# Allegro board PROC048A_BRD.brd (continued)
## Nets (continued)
3V3_A: C11.1 C40.1 C41.1 FL4.1 L3.2 R14.1
5V: C25.2 C26.2 C27.1 C28.1 C99.1 C100.1 D1.2(ANODE) D2.2(ANODE) D3.2(ANODE) D4.2(ANODE) FL8.2 LD10.2(ANODE) R1.2 R2.2 U1.11(PVIN1) U1.12(PVIN2) U1.13(PVIN3) U1.14(PVIN4) U2.11(PVIN1) U2.12(PVIN2) U2.13(PVIN3) U2.14(PVIN4)
GND: C1.2 C2.2 C3.2 C4.2 C7.2 C8.2 C9.2 C12.2 C13.2 C14.2 C15.2 C16.2 C17.2 C22.2 C23.2 C24.2 C25.1 C26.1 C27.2 C28.2 C29.2 C30.2 C31.2 C32.2 C33.2 C34.2 C35.2 C36.2 C37.2 C38.2 C39.2 C40.2 C41.2 C42.2 C43.2 C44.2 C45.2 C46.2 C47.2 C48.2 C49.1 C50.1 C51.2 C52.2 C53.2 C54.2 C55.2 C56.2 C57.2 C59.2 C60.2 C61.2 C62.2 C63.2 C64.2 C65.2 C66.2 C67.2 C68.2 C69.2 C70.2 C71.2 C72.2 C73.2 C74.1 C75.1 C76.2 C77.2 C78.2 C79.1 C80.1 C81.1 C82.2 C83.2 C84.1 C85.2 C86.2 C87.2 C88.2 C89.1 C90.2 C91.2 C92.2 C93.2 C94.2 C95.1 C96.1 C97.2 C98.2 C99.2 C100.2 C101.2 C102.2 C103.2 C104.2 C105.2 C106.2 C107.2 C108.2 C109.2 C110.2 C111.2 C112.2 C113.2 C114.2 C115.2 C116.1 C117.2 C118.1 C119.1 C120.1 C121.2 C122.1 C123.2 C124.2 C125.1 C126.2 C127.1 C128.1 C129.2 C130.2 C131.2 C132.1 C133.1 C134.1 C135.2 C136.2 C137.1 C138.1 C139.2 C140.1 C141.2 C142.1 C143.1 C144.2 C145.1 C146.1 C147.2 C148.1 C149.1 C150.1 C151.1 C152.2 C153.1 C154.2 C155.2 C156.2 C157.2 C158.1 C159.2 C160.2 C161.1 C162.1 C163.2 C164.1 C165.2 C166.1 C167.2 C168.1 C169.1 C170.1 C171.1 C172.2 C173.1 C174.2 C175.2 C176.1 C177.2 C178.2 C179.2 C180.2 C181.2 C182.2 C183.2 C184.1 C185.1 C186.2 C187.2 C188.1 C189.2 C190.2 C191.1 C192.1 C193.2 C194.1 C195.2 C196.2 C197.2 C198.2 C199.2 C200.1 C201.2 C202.1 C203.2 C204.2 C205.2 C206.1 C207.2 C208.2 C209.1 C210.1 C211.1 C212.1 C213.2 C214.1 C215.2 C216.2 D5.2(ANODE) D6.2(ANODE) D7.2(ANODE) D8.2(ANODE) D9.3(GND) D10.2 D11.3(GND) D12.2 D13.2 D14.2 D15.2(A) D16.2(ANODE) FL7.1 J1.5 J2.2 J2.3 J3.18 J3.24 J3.30 J3.36 J3.42 J3.48 J3.54 J3.60 J3.61 J3.62 J3.63 J3.64 J4.4 J4.5 J5.6(VSS) J5.12(CD2) Q1.2(EMITTER) R13.2 R15.2 R18.2 R19.2 R21.2 R25.1 R27.1 R39.2 R42.1 R44.2 R46.2 R49.2 R56.1 R59.1 R66.1 R109.1 R135.2 R155.2 R185.1 R187.1 R188.1 R190.2 R196.2 R205.2 R206.2 R207.2 S1.2 S1.3 S1.4 SW1.4 SW1.5 SW1.6 SW2.9 SW2.10 SW2.11 SW2.12 SW2.13 SW2.14 SW2.15 SW2.16 SW4.3 SW4.4 SW5.3 SW5.4 SW6.3 SW6.4 SW7.3 SW7.4 TP5.1(TP) TP32.1(TP) TP33.1(TP) U1.5(GND) U1.17(DAP) U2.5(GND) U2.17(DAP) U3.1(GND1) U3.5(GND2) U3.10(AGND) U3.11(GND3) U3.13(TEST) U3.15(GND4) U3.25(GND5) U3.35(GND6) U3.47(GND7) U3.51(GND8) U4.5(VSS) U5.4(GND) U5.9(EPAD) U6.65(EP) U7.4(GND) U8.3(GND) U9.3(GND) U10.A1(VSS#A1) U10.A8(VSS#A8) U10.B1(VSS#B1) U10.B2(VSSQ#B2) U10.B8(VSSQ#B8) U10.C9(VSSQ#C9) U10.D1(VSSQ#D1) U10.D8(VSS#D8) U10.D9(VSSQ#D9) U10.F2(VSS#F2) U10.F8(VSS#F8) U10.J1(VSS#J1) U10.J9(VSS#J9) U10.L1(VSS#L1) U10.L9(VSS#L9) U10.N1(VSS#N1) U10.N9(VSS#N9) U11.A1(VSS#A1) U11.A8(VSS#A8) U11.B1(VSS#B1) U11.B2(VSSQ#B2) U11.B8(VSSQ#B8) U11.C9(VSSQ#C9) U11.D1(VSSQ#D1) U11.D8(VSS#D8) U11.D9(VSSQ#D9) U11.F2(VSS#F2) U11.F8(VSS#F8) U11.J1(VSS#J1) U11.J9(VSS#J9) U11.L1(VSS#L1) U11.L9(VSS#L9) U11.N1(VSS#N1) U11.N9(VSS#N9) U12.B7(GND#B7) U12.B14(GND#B14) U12.C19(GND#C19) U12.D4(GND#D4) U12.F7(GND#F7) U12.F8(GND#F8) U12.F13(GND#F13) U12.F14(GND#F14) U12.G4(GND#G4) U12.G6(GND#G6) U12.G7(GND#G7) U12.G8(GND#G8) U12.G9(GND#G9) U12.G10(GND#G10) U12.G11(GND#G11) U12.G12(GND#G12) U12.G13(GND#G13) U12.G14(GND#G14) U12.G15(GND#G15) U12.G17(GND#G17) U12.H19(GND#H19) U12.J2(GND#J2) U12.J7(GND#J7) U12.J9(GND#J9) U12.J10(GND#J10) U12.J11(GND#J11) U12.J12(GND#J12) U12.J14(GND#J14) U12.K6(GND#K6) U12.K7(GND#K7) U12.K9(GND#K9) U12.K10(GND#K10) U12.K11(GND#K11) U12.K12(GND#K12) U12.K14(GND#K14) U12.K15(GND#K15) U12.L9(GND#L9) U12.L10(GND#L10) U12.L11(GND#L11) U12.L12(GND#L12) U12.M2(GND#M2) U12.M7(GND#M7) U12.M9(GND#M9) U12.M10(GND#M10) U12.M11(GND#M11) U12.M12(GND#M12) U12.M14(GND#M14) U12.M16(GND#M16) U12.N6(GND#N6) U12.N7(GND#N7) U12.N14(GND#N14) U12.N15(GND#N15) U12.P7(GND#P7) U12.P8(GND#P8) U12.P11(GND#P11) U12.P12(GND#P12) U12.P13(GND#P13) U12.P14(GND#P14) U12.R19(GND#R19) U12.U7(GNDA#U7) U12.U8(GNDA#U8) U12.U9(GNDA#U9) U12.U10(GNDA#U10) U12.U11(GNDA#U11) U12.U12(GNDA#U12) U12.U13(GNDA#U13) U12.U14(GNDA#U14) U12.V5(GNDA#V5) U12.V6(GNDA#V6) U12.V7(GNDA#V7) U12.V8(GNDA#V8) U12.V9(GNDA#V9) U12.V12(GNDA#V12) U12.V13(GNDA#V13) U12.V14(GNDA#V14) U12.V15(GNDA#V15) U12.V16(GNDA#V16) U12.V19(GNDA#V19) U12.V20(GNDA#V20) U12.W6(GNDA#W6) U12.W7(GNDA#W7) U12.W12(GNDA#W12) U12.W15(GNDA#W15) U12.W16(GNDA#W16) U12.W19(GNDA#W19) U12.W20(REFCLKN_D1) U12.Y5(HDRXP0_D0CH0) U12.Y6(HDRXN0_D0CH0) U12.Y7(HDRXP0_D0CH1) U12.Y8(HDRXN0_D0CH1) U12.Y11(REFCLKP_D0) U12.Y12(REFCLKN_D0) U12.Y14(HDRXP0_D1CH0) U12.Y15(HDRXN0_D1CH0) U12.Y16(HDRXP0_D1CH1) U12.Y17(HDRXN0_D1CH1) U12.Y19(REFCLKP_D1) U13.3(GND) U14.10(VSS) U15.1(GND#1) U15.5(GND#5) U15.10(AGND) U15.11(GND#11) U15.13(TEST) U15.15(GND#15) U15.25(GND#25) U15.35(GND#35) U15.47(GND#47) U15.51(GND#51) U16.5(GND) U17.3(GND#3) U17.8(GND#8) U18.3(GND#3) U18.8(GND#8) U19.4(PGND) U19.8(GND) U19.11(PAD) U20.5(VSS) Y1.2 Y1.4 Y3.2 Y3.4
GND_EARTH: C49.2 C50.2 R41.1
GND_SDCD: FL7.2 J5.10 J5.11 J5.13 J5.14
VCC5V_CONN: C76.1 C77.1 C78.1 C79.2 J3.1 J3.2 J3.3 SW3.3
VCC5V_EXT: J2.1 SW3.1
VCC_1V1: C10.1 C36.1 C37.1 FL2.1 L1.2 R12.1
VCC_AUX: C124.1 C137.2 C144.1 C199.1 C203.1 FL9.1 U12.F6(VCCAUX#F6) U12.F15(VCCAUX#F15) U12.P6(VCCAUX#P6) U12.P15(VCCAUX#P15) U12.V10(VCCAUXA0#V10) U12.V11(VCCAUXA0#V11) U12.V17(VCCAUXA1#V17) U12.V18(VCCAUXA1#V18)
VCC_CORE: C151.2 C160.1 C171.2 C172.1 C173.2 C174.1 C182.1 C183.1 C188.2 C194.2 FL2.2 U12.H8(VCC#H8) U12.H9(VCC#H9) U12.H10(VCC#H10) U12.H11(VCC#H11) U12.H12(VCC#H12) U12.H13(VCC#H13) U12.J8(VCC#J8) U12.J13(VCC#J13) U12.K8(VCC#K8) U12.K13(VCC#K13) U12.L8(VCC#L8) U12.L13(VCC#L13) U12.M8(VCC#M8) U12.M13(VCC#M13) U12.N8(VCC#N8) U12.N9(VCC#N9) U12.N10(VCC#N10) U12.N11(VCC#N11) U12.N12(VCC#N12) U12.N13(VCC#N13)
VCCHTX: C63.1 C64.1 C209.2 C211.2 C212.2 FL5.2 R214.1 U12.T6(VCCA0#T6) U12.T15(VCCA1#T15) U12.U6(VCCA0#U6) U12.U15(VCCA1#U15)
VCCHTX_1V1: C57.1 C58.1 FL5.1 FL6.1 R45.1 U5.1(OUT1) U5.2(OUT2)
VCCHTX_C: C200.2 C206.2 C210.2 R214.2 U12.T7(VCCHTX0_D0CH0) U12.T8(VCCHRX0_D0CH0) U12.T9(VCCHRX1_D0CH1) U12.T10(VCCHTX1_D0CH1) U12.T11(VCCHTX0_D1CH0) U12.T12(VCCHRX0_D1CH0) U12.T13(VCCHRX1_D1CH1) U12.T14(VCCHTX1_D1CH1)
12MHZ_OSCI: C31.1 U3.2(OSCI) Y1.1
12MHZ_OSCI1: C93.1 U15.2(OSCI) Y3.1
12MHZ_OSCO: C29.1 U3.3(OSCO) Y1.3
12MHZ_OSCO1: C91.1 U15.3(OSCO) Y3.3
AR1243_LVDS_MODE: R175.2 SW2.3 U12.C6(PT11A)
BST1_REGA: C19.2 D7.1(CATHODE) L2.1 U1.15(SW1)
BST1_REGB: C21.2 D8.1(CATHODE) L4.1 U2.15(SW1)
BST2_REGA: C18.2 D5.1(CATHODE) L1.1 U1.10(SW2)
BST2_REGB: C20.2 D6.1(CATHODE) L3.1 U2.10(SW2)
C_RGMII_RXC: R47.2 U6.43(RX_CLK)
C_RGMII_RXCTL: R63.2 R64.2 R66.2 U6.53(RX_DV/RX_CTRL)
C_RGMII_RXD0: R48.1 R184.2 R185.2 U6.44(RX_D0)
C_RGMII_RXD1: R60.1 U6.45(RX_D1)
C_RGMII_RXD2: R61.1 R186.1 R187.2 U6.46(RX_D2)
C_RGMII_RXD3: R62.1 U6.47(RX_D3)
C_RGMII_RXD4: R188.2 R189.1 U6.48(RX_D4/GPIO)
C_RGMII_RXD6: R59.2 R65.1 U6.50(RX_D6/GPIO)
C_RGMII_RXD7: R55.1 R56.2 U6.51(RX_D7/GPIO)
CAPTURE_START: C89.2 R151.1 R153.2 U12.U1(PB6A/D5/MISO2/IO5)
CFG0: R217.2 S1.7 U12.U4(CFG_0)
CFG1: R216.2 S1.6 U12.T4(CFG_1)
CFG2: R215.2 S1.5 U12.R4(CFG_2)
CONFIG_VIA_HW: R177.2 SW2.5 U12.A7(PT18A)
CONN_SPI_CLK: J3.9 R91.2 R92.2
CONN_SPI_CSN: J3.7 R85.2 R86.2
CONN_SPI_MISO: J3.12 R90.2 R96.2
CONN_SPI_MOSI: J3.11 R99.2 R101.2
DATA_TRANS_PROG_LED1: LD1.1(CATHODE) U12.E6(PT6A)
DDR3_A0: RA6.6 U10.K3(A0) U11.K3(A0) U12.K18(PR41D)
DDR3_A1: RA7.7 U10.L7(A1) U11.L7(A1) U12.G20(PR38D)
DDR3_A2: RA6.5 U10.L3(A2) U11.L3(A2) U12.G19(PR41A/GR_PCLK2_1)
DDR3_A3: RA9.8 U10.K2(A3) U11.K2(A3) U12.J18(PR41C/GR_PCLK2_0)
DDR3_A4: RA7.8 U10.L8(A4) U11.L8(A4) U12.J19(PR44A/PCLKT2_1/S2_OUT)
DDR3_A5: RA5.5 U10.L2(A5) U11.L2(A5) U12.J16(PR20D)
DDR3_A6: RA8.8 U10.M8(A6) U11.M8(A6) U12.E20(PR38A)
DDR3_A7: RA5.6 U10.M2(A7) U11.M2(A7) U12.K17(PR29B)
DDR3_A8: RA8.7 U10.N8(A8) U11.N8(A8) U12.J20(PR44C/PCLKT2_0/S3_IN)
DDR3_A9: RA5.7 U10.M3(A9) U11.M3(A9) U12.D20(PR35C/VREF1_2)
DDR3_A10: RA6.8 U10.H7(A10/AP) U11.H7(A10/AP) U12.K19(PR44B/PCLKC2_1)
DDR3_A11: RA8.6 U10.M7(A11) U11.M7(A11) U12.F19(PR38B)
DDR3_A12: RA7.5 U10.K7(A12/BC#) U11.K7(A12/BC#) U12.F20(PR38C)
DDR3_A13: RA5.8 U10.N3(A13) U11.N3(A13) U12.L19(PR47C/PCLKT3_0/S4_IN)
DDR3_A14: RA8.5 U10.N7(A14) U11.N7(A14) U12.K16(PR29A)
DDR3_A15: RA6.7 U10.J7(A15) U11.J7(A15) U12.J17(PR20C)
DDR3_BA0: RA9.7 U10.J2(BA0) U11.J2(BA0) U12.D19(PR35B/S2_IN)
DDR3_BA1: RA7.6 U10.K8(BA1) U11.K8(BA1) U12.C20(PR35A/S1_OUT)
DDR3_BA2: RA9.6 U10.J3(BA2) U11.J3(BA2) U12.H17(PR20B)
DDR3_CASN: RA10.7 U10.G3(CAS#) U11.G3(CAS#) U12.E19(PR35D)
DDR3_CK: R210.1 U10.F7(CK) U11.F7(CK) U12.U18(PR92A/LRC_GPLL0T_MFGOUT1)
DDR3_CKE: R191.1 U10.G9(CKE) U11.G9(CKE) U12.L20(PR47A/PCLKT3_1/S3_OUT)
DDR3_CKN: R209.1 U10.G7(CK#) U11.G7(CK#) U12.U17(PR92B/LRC_GPLL0C_MFGOUT1)
DDR3_CSN: RA9.5 U10.H2(CS#) U11.H2(CS#) U12.T17(PR92D/LRC_GPLL0C_IN/S7_OUT)
DDR3_DM0: U11.B7(DM/TDQS) U12.U19(PR89C/LRC_GPLL0T_MFGOUT2)
DDR3_DM1: U10.B7(DM/TDQS) U12.R17(PR56D)
DDR3_DQ0: U11.B3(DQ0) U12.N20(PR83B/S6_IN)
DDR3_DQ1: U11.C7(DQ1) U12.P19(PR83C)
DDR3_DQ2: U11.C2(DQ2) U12.N19(PR83A/S5_OUT)
DDR3_DQ3: U11.C8(DQ3) U12.R20(PR86B/S7_IN)
DDR3_DQ4: U11.E3(NF/DQ4) U12.U20(PR86D)
DDR3_DQ5: U11.E8(NF/DQ5) U12.P18(PR83D)
DDR3_DQ6: U11.D2(NF/DQ6) U12.U16(PR92C/LRC_GPLL0T_IN)
DDR3_DQ7: U11.E7(NF/DQ7) U12.P20(PR86A/S6_OUT)
DDR3_DQ8: U10.B3(DQ0) U12.M19(PR47D/PCLKC3_0)
DDR3_DQ9: U10.C7(DQ1) U12.L16(PR50A/GR_PCLK3_0)
DDR3_DQ10: U10.C2(DQ2) U12.R16(PR56C/S5_IN)
DDR3_DQ11: U10.C8(DQ3) U12.N17(PR56A/S4_OUT)
DDR3_DQ12: U10.E3(NF/DQ4) U12.M20(PR47B/PCLKC3_1)
DDR3_DQ13: U10.E8(NF/DQ5) U12.N18(PR53C)
DDR3_DQ14: U10.D2(NF/DQ6) U12.L18(PR50C/GR_PCLK3_1)
DDR3_DQ15: U10.E7(NF/DQ7) U12.M18(PR50D)
DDR3_DQS0: U11.C3(DQS) U12.T19(PR89A)
DDR3_DQS0N: U11.D3(DQS#) U12.R18(PR89B)
DDR3_DQS1: U10.C3(DQS) U12.N16(PR53A)
DDR3_DQS1N: U10.D3(DQS#) U12.M17(PR53B)
DDR3_ODT: RA10.8 U10.G1(ODT) U11.G1(ODT) U12.T16(PR77A)
DDR3_RASN: RA10.5 U10.F3(RAS#) U11.F3(RAS#) U12.H20(PR41B)
DDR3_RSTN: R69.2 TP13.1(TP) U10.N2(RESET#) U11.N2(RESET#) U12.H18(PR20A)
DDR3_VDD: C74.2 C75.2 C128.2 C129.1 C130.1 C134.2 C135.1 C138.2 C146.2 C152.1 C154.1 C155.1 C161.2 C164.2 C165.1 C168.2 C169.2 C170.2 C178.1 C184.2 C185.2 C186.1 C189.1 C190.1 C192.2 C193.1 C195.1 C196.1 C197.1 C198.1 C207.1 C208.1 FL10.2 U10.A2(VDD#A2) U10.A9(VDD#A9) U10.B9(VDDQ#B9) U10.C1(VDDQ#C1) U10.D7(VDD#D7) U10.E2(VDDQ#E2) U10.E9(VDDQ#E9) U10.G2(VDD#G2) U10.G8(VDD#G8) U10.K1(VDD#K1) U10.K9(VDD#K9) U10.M1(VDD#M1) U10.M9(VDD#M9) U11.A2(VDD#A2) U11.A9(VDD#A9) U11.B9(VDDQ#B9) U11.C1(VDDQ#C1) U11.D7(VDD#D7) U11.E2(VDDQ#E2) U11.E9(VDDQ#E9) U11.G2(VDD#G2) U11.G8(VDD#G8) U11.K1(VDD#K1) U11.K9(VDD#K9) U11.M1(VDD#M1) U11.M9(VDD#M9)
DDR3_VREF: C132.2 R199.1 U19.6(REFOUT)
DDR3_VTT: C113.1 C114.1 C115.1 C116.2 C117.1 C118.2 C119.2 C120.2 C121.1 C122.2 C123.1 C133.2 C136.1 C141.1 C145.2 C150.2 C157.1 C179.1 C180.1 C181.1 R191.2 R197.1 RA5.1 RA5.2 RA5.3 RA5.4 RA6.1 RA6.2 RA6.3 RA6.4 RA7.1 RA7.2 RA7.3 RA7.4 RA8.1 RA8.2 RA8.3 RA8.4 RA9.1 RA9.2 RA9.3 RA9.4 RA10.1 RA10.2 RA10.3 RA10.4 U19.3(VO) U19.5(VOSNS)
DDR3_WEN: RA10.6 U10.H3(WE#) U11.H3(WE#) U12.K20(PR44D/PCLKC2_0)
DDR_1V35: C5.1 C38.1 C39.1 FL3.1 L2.2 R10.1
DDR_FULL_LED7: LD6.1(CATHODE) U12.E10(PT56B)
DMM_CLK: J3.15 R94.2
DMM_CLK_C: R94.1 U12.G1(PL47D/PCLKC6_0)
DMM_MUX_CTL: J3.16 R120.2
DMM_MUX_CTL_C: R120.1 U12.P5(PL83D/D14/IO14)
DMM_SYNC: J3.17 R95.2
DMM_SYNC_C: R95.1 U12.H2(PL47C/PCLKT6_0)
DONE: R104.2 R107.2 TP2.1(TP) U12.Y3(DONE)
DP0: J3.19 RA1.5
DP0_C: RA1.4 U12.H1(PL53C)
DP1: J3.21 RA1.6
DP1_C: RA1.3 U12.J1(PL53B)
DP2: J3.23 RA1.7
DP2_C: RA1.2 U12.K1(PL53D)
DP3: J3.25 RA1.8
DP3_C: RA1.1 U12.K2(PL53A)
DP4: J3.27 RA2.5
DP4_C: RA2.4 U12.K3(PL50D)
DP5: J3.29 RA2.6
DP5_C: RA2.3 U12.K4(PL56A)
DP6: J3.31 RA2.7
DP6_C: RA2.2 U12.J5(PL50B)
DP7: J3.33 RA2.8
DP7_C: RA2.1 U12.K5(PL56B/VREF1_6)
DP8: J3.35 RA3.5
DP8_C: RA3.4 U12.J4(PL50A/GR_PCLK6_0)
DP9: J3.37 RA3.6
DP9_C: RA3.3 U12.L5(PL56D)
DP10: J3.39 RA3.7
DP10_C: RA3.2 U12.J3(PL50C/GR_PCLK6_1)
DP11: J3.41 RA3.8
DP11_C: RA3.1 U12.M4(PL83A)
DP12: J3.43 RA4.5
DP12_C: RA4.4 U12.L4(PL56C)
DP13: J3.45 RA4.6
DP13_C: RA4.3 U12.N4(PL83C/D15/IO15)
DP14: J3.47 RA4.7
DP14_C: RA4.2 U12.N5(PL83B)
DP15: J3.49 RA4.8
DP15_C: RA4.1 U12.M5(PL77A)
ECP5U_VREF: C213.1 C214.2 R192.2 R194.1 R196.1 U12.P16(PR56B/VREF1_3)
EEPROM_ADD: R50.2 U7.3(A2) U12.E12(PT74B/GR_PCLK1_1)
EEPROM_RD_FAIL_LED6: LD9.1(CATHODE) U12.C11(PT65B/PCLKC0_0)
EEPROM_WP: R49.1 U7.7(WP) U12.A12(PT76A)
ETH_D0N: J6.10(TD0-) U6.3(TD_M_A) U18.5(D2-) U18.6(NC1)
ETH_D0P: J6.9(TD0+) U6.2(TD_P_A) U18.4(D2+) U18.7(NC2)
ETH_D1N: J6.8(TD1-) U6.6(TD_M_B) U18.2(D1-) U18.9(NC3)
ETH_D1P: J6.7(TD1+) U6.5(TD_P_B) U18.1(D1+) U18.10(NC4)
ETH_D2N: J6.6(TD2-) U6.11(TD_M_C) U17.5(D2-) U17.6(NC1)
ETH_D2P: J6.5(TD2+) U6.10(TD_P_C) U17.4(D2+) U17.7(NC2)
ETH_D3N: J6.4(TD3-) U6.14(TD_M_D) U17.2(D1-) U17.9(NC3)
ETH_D3P: J6.3(TD3+) U6.13(TD_P_D) U17.1(D1+) U17.10(NC4)
ETH_INT: R58.2 U6.60(INT/PWDN) U12.A15(PT103A)
FB1_REGA: C5.2 R10.2 R18.1 U1.1(FB1)
FB1_REGB: C6.2 R11.2 R19.1 U2.1(FB1)
FB2_REGA: C10.2 R12.2 R13.1 U1.8(FB2)
FB2_REGB: C11.2 R14.2 R15.1 U2.8(FB2)
FPGA_DDR3_CLK_IN_N: R71.2 U8.5(OUTPUT2) U12.A5(PL11B/ULC_GPLL0C_IN)
FPGA_DDR3_CLK_IN_P: R71.1 U8.4(OUTPUT1) U12.A4(PL11A/ULC_GPLL0T_IN)
FPGA_ERR_LED2: LD5.1(CATHODE) U12.D10(PT56A)
FPGA_HOST_INT: R97.1 U12.M3(PL86B/D12/IO12)
FPGA_MCU_RSTN: R147.2 U12.N3(PL86A/D13/IO13) U13.1(A)
FPGA_RST: C96.2 LD13.1(CATHODE) R161.1 R162.2 U12.R1(PB4A/D7/IO7)
FPGA_SPI_CS: R86.1 U12.E13(PT80B)
FPGA_SPI_MISO: R90.1 U12.D14(PT85A)
FPGA_SPI_MOSI: R99.1 U12.C14(PT83B)
FPGA_SPI_SCK: R92.1 U12.A14(PT83A)
FPGA_UART_RX: R142.1 U12.A13(PT76B)
FPGA_UART_TX: R139.1 U12.B13(PT78A)
FT_FPGA_RF_EP_I2C_SCL: R3.1 R51.2 R68.2 R81.1 R141.1 U7.6(SCL)
FT_FPGA_RF_EP_I2C_SDA: R4.1 R5.1 R52.2 R67.2 R76.1 R136.1 U7.5(SDA)
FTDI1_VDD_1V8: C97.1 U15.12(VCORE#12) U15.37(VCORE#37) U15.49(VREGOUT) U15.64(VCORE#64)
FTDI1_VPHY: C88.1 C90.1 FB4.2 U15.4(VPHY)
FTDI1_VPLL: C85.1 C86.1 FB3.2 U15.9(VPLL)
FTDI2_VCORE: C14.1 C15.1 C30.1 C32.1 U3.12(VCORE#12) U3.37(VCORE#37) U3.49(VREGOUT) U3.64(VCORE#64)
FTDI2_VPHY: C23.1 C24.1 FB2.2 U3.4(VPHY)
FTDI2_VPLL: C16.1 C17.1 FB1.2 U3.9(VPLL)
FTDI_HOST_INT: R6.1 R22.1 R100.1
FTDI_JTAG_ACT: LD15.1(CATHODE) U15.21(ADBUS4)
FTDI_JTAG_TCK: R135.1 R140.2 TP9.1(TP) U12.T5(TCK/TEST_CLK)
FTDI_JTAG_TDI: R124.2 R133.1 TP7.1(TP) U12.R5(TDI)
FTDI_JTAG_TDO: R121.2 R134.1 TP8.1(TP) U12.V4(TDO)
FTDI_JTAG_TMS: R115.1 R118.2 TP1.1(TP) U12.U5(TMS)
FTDI_MCU_RSTN: R26.1 R144.2 U13.2(B)
FTDI_UART_RXD: R146.1 U3.38(CDBUS0)
FTDI_UART_TXD: R138.1 U3.39(CDBUS1)
FTDI_USB1_DM: D11.1(D+) J4.2 R152.1
FTDI_USB1_DM_C: R152.2 U15.7(DM)
FTDI_USB1_DP: D11.2(D-) J4.3 R150.1
FTDI_USB1_DP_C: R150.2 U15.8(DP)
FTDI_USB2_DM: D9.1(D+) J1.2 R24.1
FTDI_USB2_DM_C: R24.2 U3.7(DM)
FTDI_USB2_DP: D9.2(D-) J1.3 R23.1
FTDI_USB2_DP_C: R23.2 U3.8(DP)
GPIO_PHY_RESETN: R57.2 U6.59(RESET_N) U12.A16(PT110A)
HEADER_ERR_LED4: LD8.1(CATHODE) U12.B11(PT65A/PCLKT0_0)
HOST_INT: J3.10 R97.2 R100.2
INITN: LD12.1(CATHODE) R111.2 TP3.1(TP) U12.V3(INITN)
LED_ACTN: J6.12 U6.61(LED_2)
LED_LINKN: J6.13 U6.62(LED_1)
LED_SPEED: TP12.1(TP) U6.63(LED_0)
LVDS_0M: J3.58 R203.2 U12.E3(PL20B)
LVDS_0P: J3.56 R203.1 U12.F4(PL20A)
LVDS_1M: J3.52 R198.2 U12.D5(PL17B)
LVDS_1P: J3.50 R198.1 U12.E4(PL17A)
LVDS_2M: J3.40 R84.2 U12.E1(PL38D)
LVDS_2P: J3.38 R84.1 U12.D2(PL38C)
LVDS_3M: J3.34 R200.2 U12.D3(PL17D)
LVDS_3P: J3.32 R200.1 U12.C3(PL17C)
LVDS_12BIT_MODE_ON: R223.1 SW1.1 U12.A6(PT4A/ULC_GPLL1T_IN)
LVDS_14BIT_MODE_ON: R222.1 SW1.2 U12.B6(PT4B/ULC_GPLL1C_IN)
LVDS_16BIT_MODE_ON: R224.1 SW1.3 U12.D7(PT9B)
LVDS_CAPTURE: R173.2 SW2.1 U12.E8(PT13A)
LVDS_CLKM: J3.46 R208.2 U12.F3(PL44B/PCLKC7_1)
LVDS_CLKP: J3.44 R208.1 U12.G3(PL44A/PCLKT7_1)
LVDS_FRCLKN: J3.28 R204.2 U12.E2(PL44D/PCLKC7_0)
LVDS_FRCLKP: J3.26 R204.1 U12.F2(PL44C/PCLKT7_0)
LVDS_PATH_ERR_LED3: LD7.1(CATHODE) U12.A11(PT63B/PCLKC0_1)
LVDS_VALIDM: J3.22 R82.2 U12.B3(PL14D)
LVDS_VALIDP: J3.20 R82.1 U12.A3(PL14C)
MCU_RSTN: J3.59 R143.2
MDIO_MDC: R75.1 R183.2 U6.20(MDC)
MDIO_MDIO: R73.1 R181.2 U6.21(MDIO)
MEM_VREF: C139.1 C140.2 C159.1 C162.2 R190.1 R193.2 R195.2 U10.E1(VREFDQ) U10.J8(VREFCA) U11.E1(VREFDQ) U11.J8(VREFCA)
OSC_CLKEN: R54.1 U12.E5(PL20C)
PG: R201.2 U19.9(PGOOD)
PGOOD: R98.1 U12.L2(PL86D/D10/IO10)
PHY_JTAG_RESET: R39.1 U6.24(JTAG_TRSTN)
PROGRAMN: C81.2 LD11.1(CATHODE) R114.1 R117.2 R132.2 TP6.1(TP) U12.W3(PROGRAMN)
RAW_MODE: R176.2 SW2.4 U12.C8(PT15A)
RF_CONN_SPI_CS: R85.1 U3.19(ADBUS3)
RF_CONN_SPI_MISO: R7.2 R96.1 U3.18(ADBUS2)
RF_CONN_SPI_MOSI: R101.1 U3.17(ADBUS1)
RF_CONN_SPI_SCK: R91.1 U3.16(ADBUS0)
RGMII_CLKOUT: R182.1 U12.A19(PT121A/URC_GPLL1T_IN)
RGMII_RXC: R47.1 U12.D11(PT69A/PCLKT1_1)
RGMII_RXCTL: R63.1 U12.B20(PT121B/URC_GPLL1C_IN)
RGMII_RXD0: R48.2 U12.B17(PT114A)
RGMII_RXD1: R60.2 U12.D16(PT112B)
RGMII_RXD2: R61.2 U12.A17(PT116A)
RGMII_RXD3: R62.2 U12.E15(PT107B)
RGMII_TXC: R74.1 U6.40(GTX_CLK)
RGMII_TXCTL: U6.52(TX_EN/TX_CTRL) U12.D15(PT107A)
RGMII_TXD0: R80.1 U6.38(TX_D0)
RGMII_TXD1: R78.1 U6.37(TX_D1)
RGMII_TXD2: R77.1 U6.36(TX_D2)
RGMII_TXD3: R79.1 U6.35(TX_D3)
RS232RX: J3.55 R142.2 R146.2
RS232TX: J3.57 R138.2 R139.2
SCL: J3.53 R141.2
SD_CD: D15.1(K) J5.9(CD1) R172.2 U12.C15(PT105B)
SD_CLK: J5.5(CLK) R72.2 U16.3(IO3)
SD_CMD: J5.3(CMD) R32.2 U12.E9(PT20B) U16.6(IO4)
SD_DAT0: J5.7(DAT0) R28.2 U12.D9(PT20A) U16.2(IO2)
SD_DAT1: J5.8(DAT1) R29.2 U12.C10(PT58B) U16.1(IO1)
SD_DAT2: J5.1(DAT2) R34.2 U12.A9(PT60A/GR_PCLK0_1) U16.8(IO6)
SD_DAT3: J5.2(CD/DAT3) R33.2 U12.B9(PT58A) U16.7(IO5)
SD_DETECT_LED5: LD2.1(CATHODE) U12.D6(PT6B)
SD_FULL_LED0: LD3.1(CATHODE) U12.C9(PT54A)
SD_STORE: R174.2 SW2.2 U12.C7(PT11B)
SDA: J3.51 R136.2
SPARE_GPIO_SW: C95.2 R159.1 R160.2 U12.T1(PB4B/D6/IO6)
SPARE_LED8: LD4.1(CATHODE) U12.E7(PT9A)
SPI_CS_N: R156.1 U12.R2(PB15A/HOLDN/DI/BUSY/CSSPIN/CEN)
SPI_HOLD_N: R148.1 U12.W1(PB9A/D3/IO3)
SPI_MISO: R157.1 U12.V2(PB11A/D1/MISO/IO1)
SPI_MOSI: R126.1 U12.W2(PB11B/D0/MOSI/IO0)
SPI_SCK: R125.2 R213.1 U14.16(C)
SPI_WP_N: R127.1 U12.Y2(PB9B/D2/IO2)
SYS_CLK100_N: R88.2 U9.5(OUTPUT2) U12.F1(PL47B/PCLKC6_1)
SYS_CLK100_P: R88.1 U9.4(OUTPUT1) U12.G2(PL47A/PCLKT6_1)
USB1_CS: R218.2 U15.63(EECS) U20.1(CS)
USB1_DI: R220.2 U15.61(EEDATA) U20.3(DI)
USB1_DO: R220.1 R221.2 U20.4(DO)
USB1_SCK: R219.2 U15.62(EECLK) U20.2(CLK)
USB2_CS: R31.2 U3.63(EECS) U4.1(CS)
USB2_DI: R35.2 U3.61(EEDATA) U4.3(DI)
USB2_DO: R35.1 R37.2 U4.4(DO)
USB2_SCK: R30.2 U3.62(EECLK) U4.2(CLK)
USER_SW1: R178.2 SW2.6 U12.B8(PT15B)
USER_SW2: R179.2 SW2.7 U12.A8(PT18B)
USER_SW3: R180.2 SW2.8 U12.D8(PT13B)
N35698: J6.SH1 J6.SH2 R41.2
N35954: J6.1(CH-GND) R42.2
N35962: J6.11 R70.2
N36046: J6.14 R40.2
N40882: C44.1 R38.1 U6.19(X_I) Y2.1
N40902: C51.1 R38.2 U6.18(X_O) Y2.2
N41020: R182.2 U6.22(CLK_OUT)
N41650: TP11.1(TP) U6.17(VDDA1P8#17) U6.64(VDDA1P8#64)
N44878: R44.1 U6.15(RBIAS)
N70149: R155.1 U15.6(REF)
N70296: R145.2 U15.14(RESET#)
N76086: R140.1 U15.16(ADBUS0)
N76092: R124.1 U15.17(ADBUS1)
N76288: R121.1 U15.18(ADBUS2)
N76294: R118.1 U15.19(ADBUS3)
N77950: LD15.2(ANODE) R154.2
N12057923: C163.1 R209.2 R210.2
N12082124: R213.2 U12.U3(CCLK/MCLK/SCK)
N12141516: R25.2 U3.6(REF)
N12141647: R20.2 U3.14(R\E\S\E\T\)
N12198012: R53.2 R54.2 U8.1(TRI-STATE)
N12285548: J3.13 R98.2
N12367018: TP17.1(TP) U12.W11(RESERVED#W11)
N12367024: TP20.1(TP) U12.W10(RESERVED#W10)
N12367080: TP14.1(TP) U12.W4(HDTXP0_D0CH0)
N12367084: TP23.1(TP) U12.W5(HDTXN0_D0CH0)
N12367136: TP22.1(TP) U12.W8(HDTXP0_D0CH1)
N12367140: TP21.1(TP) U12.W9(HDTXN0_D0CH1)
N12367168: TP19.1(TP) U12.W13(HDTXP0_D1CH0)
N12367248: TP16.1(TP) U12.W14(HDTXN0_D1CH0)
N12367252: TP18.1(TP) U12.W17(HDTXP0_D1CH1)
N12367256: TP15.1(TP) U12.W18(HDTXN0_D1CH1)
N12556752: R6.2 U3.32(BDBUS5)
N12556756: R22.2 U3.34(BDBUS7)
N12556864: R5.2 U3.27(BDBUS1)
N12556868: R4.2 U3.28(BDBUS2)
N12563455: R26.2 U3.45(CDBUS6)
N15277458: R43.2 U5.5(EN)
N15277487: C53.1 U5.6(NR)
N15279182: C58.2 R45.2 R46.1 U5.3(FB/SNS)
N15280631: C2.1 R1.1 R8.1 R16.1 U1.4(AVIN)
N15281998: R16.2 U1.3(EN1)
N15282067: R8.2 U1.6(EN2)
N15282531: C12.1 U1.2(SS1)
N15282538: C1.1 U1.7(SS2)
N15283211: C18.1 D1.1(CATHODE) U1.9(BST2)
N15283215: C19.1 D2.1(CATHODE) U1.16(BST1)
N15294700: C21.1 D4.1(CATHODE) U2.16(BST1)
N15294712: C20.1 D3.1(CATHODE) U2.9(BST2)
N15294756: C4.1 R2.1 R9.1 R17.1 U2.4(AVIN)
N15294840: R17.2 U2.3(EN1)
N15294864: R9.2 U2.6(EN2)
N15294982: C13.1 U2.2(SS1)
N15294990: C3.1 U2.7(SS2)
N15331843: C148.2 R207.1 R211.2 U19.1(REFIN)
N15331979: R202.2 U19.7(EN)
N15354055: R194.2 R195.1 R197.2 R199.2
N15358263: R83.2 U9.1(TRI-STATE)
N15366217: LD11.2(ANODE) R87.2
N15366273: LD13.2(ANODE) R93.2
N15366361: LD14.2(ANODE) R103.2
N15366449: LD14.1(CATHODE) Q1.3(COLLECTOR)
N15366479: Q1.1(BASE) R104.1
N15371882: D12.1 R151.2 SW5.1 SW5.2
N15373103: D14.1 R161.2 SW7.1 SW7.2
N15375282: D13.1 R159.2 SW6.1 SW6.2
N15376242: D10.1 R114.2 SW4.1 SW4.2
N15385918: J4.SH1 J4.SH2 J4.SH3 J4.SH4 R109.2
N15385952: J4.1 TP30.1(TP)
N15394436: J1.1 TP31.1(TP)
N15394548: J1.SH1 J1.SH2 J1.SH3 J1.SH4 R27.2
N15403136: R143.1 U13.4(Y)
N15568992: R205.1 U11.H8(ZQ)
N15578317: R206.1 U10.H8(ZQ)
N15683813: J6.2(VCC) TP10.1(TP)
N15696938: R3.2 U3.26(BDBUS0)
N15697022: R76.2 U12.C13(PT78B)
N15697026: R81.2 U12.D13(PT80A)
N15801768: R73.2 U12.E11(PT69B/PCLKC1_1)
N15802042: R80.2 U12.B19(PT119B)
N15802046: R78.2 U12.A18(PT119A)
N15802050: R77.2 U12.C17(PT114B)
N15802054: R79.2 U12.B18(PT116B)
N15802227: R74.2 U12.B12(PT71A/PCLKT1_0)
N15802298: R75.2 U12.C12(PT71B/PCLKC1_0)
N15837314: LD12.2(ANODE) R89.2
N15837897: R72.1 U12.B10(PT60B/GR_PCLK0_0)
N15863331: LD3.2(ANODE) R169.1
N15864243: LD1.2(ANODE) R171.1
N15865404: LD5.2(ANODE) R167.1
N15865498: LD7.2(ANODE) R165.1
N15865593: LD8.2(ANODE) R164.1
N15870131: LD2.2(ANODE) R170.1
N15870370: LD9.2(ANODE) R163.1
N15870464: LD6.2(ANODE) R166.1
N15870575: LD4.2(ANODE) R168.1
N16168033: TP27.1(TP) U12.A2(PL35A)
N16168037: TP28.1(TP) U12.B1(PL35B)
N16178955: TP29.1(TP) U12.V1(PB6B/D4/MOSI2/IO4)
N16278938: LD10.1(CATHODE) R21.1
N16279120: C109.1 C110.1 C112.1 C126.1 D16.1(CATHODE) F1.2 FL8.1
N16279144: F1.1 SW3.2(COMM)
N16403293: R156.2 R158.2 U14.7(S#)
N16403351: R148.2 R149.2 U14.1(DQ3)
N16403393: R127.2 R131.2 U14.9(W#/DQ2)
N16403481: R126.2 U14.15(DQ0)
N16403515: R157.2 U14.8(DQ1)

Pads without a net: J1 4; J3 4 5 6 8 14; S1 1 8; U3 21 22 23 24 29 30 33 36 40 41 43 44 46 48 52 53 54 55 57 58 59 60; U4 7; U6 1 7 9 16 25 26 27 28 30 31 32 33 34 39 49 54 55 56; U7 1 2; U8 2; U9 2; U10 A3 A7 F1 F9 H1 H9; U11 A3 A7 F1 F9 H1 H9; U12 A10 B2 B4 B5 B15 B16 C1 C2 C4 C5 C16 C18 D1 D12 D17 D18 E14 E16 E17 E18 F5 F16 F17 F18 G5 G16 G18 H3 H4 H5 H16 L1 L3 M1 N1 N2 P1 P2 P3 P4 R3 T2 T3 U2; U14 3 4 5 6 11 12 13 14; U15 22 23 24 26 27 28 29 30 32 33 34 36 38 39 40 41 43 44 45 46 48 52 53 54 55 57 58 59 60; U16 4 9; U20 7

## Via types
v1: diameter 0.457, hole 0.203, TOP to BOTTOM, 1382 vias

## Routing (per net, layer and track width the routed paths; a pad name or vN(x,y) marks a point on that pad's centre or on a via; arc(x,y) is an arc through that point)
1V1: length 18.2
  TOP w0.305: U6.8 72.7,59.57 72.82,59.69 C59.1 ; 63.63,67.01 63.63,65.52 ; 58.34,59.07 U6.42 ; U6.58 66.63,53.27 66.64,53.26 66.64,53.13 67.28,52.5 67.28,51.72 C71.1
  TOP w0.381: C45.1 61.74,67.66 v1(61.69,67.61) ; C45.1 C46.1 63.63,67.01 ; C45.1 62.45,67.48 v1(62.96,66.98) ; C61.1 57.58,59.78 v1(57.45,59.91) ; C61.1 57.43,59.08 57.43,58.11 C106.1 57.83,58.47 v1(58.13,58.47) ; C61.1 58.19,59.23 58.34,59.07 ; v1(66.52,52.12) 67.04,51.6 C71.1 ; C59.1 C60.1
  BOTTOM w0.381: v1(57.45,59.91) 57.58,59.78 C61.1
  vias: v1(53.43,57.2) v1(53.36,56.26) v1(54.4,56.26) v1(54.45,57.32) v1(75.53,59.61) v1(76.17,59.1)
1V35: length 23.5
  TOP w0.356: U12.P17 v1(49,30.71) ; U12.T18 v1(49.8,29.11) ; v1(51.66,29.11) 51.26,29.51 U12.T20 ; U12.L15 v1(46.6,33.11) U12.L14 ; U12.H15 v1(47.4,36.31) ; U12.L17 v1(49,33.11) ; U12.M15 v1(47.4,32.31) ; U12.J15 v1(47.4,35.51) ; U12.H14 v1(46.6,36.31)
  TOP w0.381: R69.1 v1(78.71,49.83)
  L05_PWR1 w0.381: 47.47,33.7 47.19,33.7 v1(46.6,33.11) v1(47.4,32.31) ; v1(46.6,36.31) v1(47.4,36.31)
  BOTTOM w0.254: U19.2 93.81,34.98
  BOTTOM w0.381: C143.2 50.16,37.56 v1(49.8,37.91) ; R193.1 v1(88.63,44.74) R192.1 ; v1(52.47,31.71) C191.2 C204.1 52.05,29.76 51.66,29.37 v1(51.66,29.11) ; v1(47.4,35.51) v1(47.4,36.31) 47.76,36.67 C149.2 ; C177.1 48.84,33.83 C176.2 48.81,33.3 v1(49,33.11) ; R211.1 v1(97.88,35.61)
  vias: v1(32.62,66.26) v1(32.62,65.1) v1(32.62,63.93) v1(33.79,65.1) v1(33.79,63.93) v1(34.96,65.1) v1(34.96,63.93) v1(36.13,66.26) v1(36.13,65.1) v1(36.13,63.93) v1(92.65,31.01) v1(92.65,29.84) v1(93.82,33.35) v1(93.82,32.18) v1(93.82,31.01) v1(93.82,29.84) v1(94.99,31.01) v1(94.99,29.84)
2V5: length 18.5
  TOP w0.305: U6.12 73.82,61.57 ; U6.4 72.62,57.57 73.54,56.65 C65.1
  TOP w0.356: U12.J6 v1(39.4,35.51) ; U12.H6 v1(39.4,36.31) ; U12.H7 v1(40.2,36.31)
  TOP w0.381: R43.1 56.2,64.69 v1(56.41,64.89) ; v1(73.93,55.93) C67.1 ; v1(36.98,44.7) 36.98,45.57 C72.1 37,46.22 37.25,46.48 U8.6 ; v1(37.31,52.37) 37.05,52.12 R53.1 ; 73.82,61.57 C55.1
  BOTTOM w0.381: v1(39.4,36.31) v1(39.4,35.51) ; v1(39.4,36.31) 39.25,36.16 C153.2 38.64,36.23 38.62,36.24 C156.1 ; v1(39.4,36.31) v1(40.2,36.31) ; v1(73.5,62.15) 73.5,62.66 73.63,62.78 C54.1 ; v1(34,35.99) C158.2 ; v1(74.39,54.28) 74.34,54.32 74.26,54.32 73.93,54.66 C67.1
  vias: v1(30.96,52.37) v1(30.96,51.2) v1(32.12,53.54) v1(32.12,52.37) v1(33.29,53.54) v1(33.29,52.37) v1(34.46,52.37) v1(51,68.14) v1(51,66.98) v1(52.16,68.14) v1(52.16,66.98) v1(53.43,68.14) v1(53.43,66.98) v1(54.6,68.14) v1(54.6,66.98) v1(73.5,54.28) v1(74.24,62.1)
2V5_A: length 26.2
  TOP w0.381: C6.1 v1(58.77,92.06) ; R11.1 v1(58.77,90.92)
  BOTTOM w0.381: v1(58.77,92.06) v1(58.77,90.92) 58.83,90.92 59.66,90.09 59.66,70.91 58.41,69.67 v1(58.41,68.14)
3V3: length 176.5
  TOP w0.254: U13.5 38.12,18.64 38.07,18.59 37.51,18.59 C84.2 ; C8.1 U3.31 ; C33.1 75.67,76.74 75.2,77.21 U3.50 ; U3.20 C9.1 ; U3.42 C22.1 ; C34.1 78.2,76.7 78.2,76.71 U3.56
  TOP w0.305: C56.1 57.63,60.75 58.81,59.57 U6.41 ; U15.50 68.47,6.65 68.47,6.65 C98.1 ; U15.56 71.47,7.35 71.67,7.15 C216.1 ; U15.31 C82.1 ; U15.42 C87.1 ; C83.1 73.95,21.52 73.97,21.5 U15.20 ; 66.13,52.87 U6.57 ; 66.63,66.73 U6.23
  TOP w0.356: U12.F12 v1(45,37.91) ; U12.P9 v1(41.8,30.71) ; U12.F10 v1(42.6,37.91) ; U12.F9 v1(41.8,37.91) ; U12.L7 v1(40.2,33.11) ; U12.L6 v1(39.4,33.11) ; U12.P10 v1(42.6,30.71) ; U12.M6 v1(39.4,32.31) ; U12.F11 v1(44.2,37.91)
  TOP w0.381: R65.2 56.23,48.69 v1(56.1,48.56) ; R132.1 v1(82.39,20.49) ; v1(69.23,70.48) 69.67,70.91 R34.1 ; C47.1 67.4,67.66 67.41,67.64 67.47,67.64 C48.1 67.5,67.64 67.96,67.64 v1(68.3,67.99) ; C47.1 66.3,67.06 66.63,66.73 ; C47.1 66.03,67.66 65.65,67.28 v1(65.65,67.1) ; v1(87.98,20.87) 87.98,20.09 R134.2 ; v1(96.49,67.1) 96.39,67 R40.1 ; C83.1 v1(73.95,22.78) ; C82.1 v1(69.18,21.64) ; C87.1 v1(63.98,12.75) ; C94.1 C92.1 U14.2 ; C94.1 51.78,6.9 v1(51.28,6.9) ; C94.1 51.4,7.79 v1(51.28,7.79) ; C33.1 v1(76.51,76.16) ; R153.1 v1(5.03,12.99) ; v1(44.16,18.97) 44.16,19.24 43.78,19.63 R144.1 ; v1(38.6,55.22) 38.4,55.42 R51.1 ; R58.1 69.82,50.34 v1(70.2,49.96) ; R7.1 v1(82.6,92.15) ; v1(84.55,28.11) 83.87,28.8 R107.1 ; R20.1 v1(86.1,89.94) ; TP4.1 91.28,24.61 91.28,23.92 91.79,23.41 C80.2 ; v1(38.6,54.05) 38.5,54.15 R52.1 ; C22.1 70.36,82.95 v1(70.07,83.23) ; R70.1 v1(92.65,46.41) ; v1(70.45,75.36) 70.39,75.42 R29.1 ; R31.1 v1(84.68,75.04) ; C7.1 73.95,90.79 v1(74.26,90.47) ; C7.1 73.56,91.29 73.25,90.98 v1(73.25,90.98) ; C7.1 C8.1 ; v1(46.32,47.04) 46.53,47.25 R67.1 ; R103.1 v1(91.7,29.09) 91.7,28.52 91.74,28.48 R111.1 ; v1(43.29,63.93) 40.86,63.93 39.85,62.91 29.18,62.91 26.94,60.67 R50.1 ; R117.1 v1(5.17,24.43) ; R28.1 70.2,76.97 v1(70.2,77.14) ; R154.1 12.99,12.99 v1(13.54,12.99) ; C34.1 78.67,76.16 v1(78.96,75.87) ; v1(83.53,16.56) 83.66,16.43 FB3.1 ; R30.1 v1(82.07,75.08) ; v1(92.34,72.77) C35.1 92.28,73.51 U4.8 ; v1(48.48,48.18) 48.61,48.05 R68.1 ; R158.1 v1(56.74,6.9) ; R32.1 76.42,73.07 v1(76.68,73.33) ; C216.1 v1(72.48,6.52) ; R57.1 68.5,50.08 v1(68.4,49.98) ; R162.1 v1(23.12,7.9) ; R131.1 62.96,20.49 v1(63.21,20.75) ; v1(79.89,91.05) 79.89,91.06 80.12,91.29 C9.1 ; R149.1 v1(49.2,19.14) ; R133.2 v1(85.44,20.16) ; R115.2 v1(76.04,25.62) ; R33.1 v1(76.55,72.06) ; v1(36.26,58.72) 36.46,58.72 36.85,58.34 C62.1 U7.8 ; U9.6 30.96,39.64 30.96,39.85 C73.1 29.76,40.86 29.3,41.32 v1(29.26,41.32) 29.26,41.49 28.88,41.87 R83.1 ; R55.2 58.39,51.66 v1(58.85,52.12) ; C98.1 68.34,6.65 v1(67.79,6.65) ; R145.1 v1(82.24,18.23) ; C69.1 63.99,51.6 v1(63.85,51.74) ; C69.1 64.61,51.86 64.99,52.24 v1(65.12,52.24) ; C69.1 C70.1 65.75,52.5 66.13,52.87 ; C84.2 37.77,18.08 v1(38.07,18.08) ; R64.1 57.98,50.08 v1(57.68,49.78) ; R37.1 v1(81.88,68.88) ; R147.1 v1(43.02,18.48) ; U4.6 v1(92.36,70.97) ; C56.1 57.58,60.93 v1(56.99,61.51) ; R160.1 v1(12.48,8.37) ; R125.1 v1(50.13,22.44)
  L06_PWR2 w0.889: 90.26,24.3 TP4.1 ; TP4.1 90.26,26.95 ; TP4.1 88.94,25.62 ; TP4.1 91.59,25.62
  BOTTOM w0.254: U19.10 94.31,39.67 94.87,40.23 C131.1
  BOTTOM w0.305: U16.10 C101.1
  BOTTOM w0.381: C131.1 v1(95.68,40.23) ; v1(35.27,33.19) 35.4,33.32 C166.2 ; C205.1 37.13,29.79 v1(37,29.91) ; v1(56.1,49.83) 55.97,49.96 R186.2 ; U20.8 C215.1 v1(59.28,16.01) ; R223.2 v1(4.67,83.49) ; v1(39.4,33.11) 39.04,33.48 39.04,33.64 C175.1 ; v1(39.4,33.11) v1(39.4,32.31) ; v1(39.4,33.11) v1(40.2,33.11) ; R189.2 52.55,50.08 v1(52.29,49.83) ; U20.6 v1(60.63,13.47) ; v1(41.8,37.91) v1(42.6,37.91) 43.01,38.32 C142.2 43.79,38.32 v1(44.2,37.91) v1(45,37.91) 45.72,37.91 C147.1 ; R181.1 70.49,65.78 v1(70.51,65.81) ; R201.1 v1(93.69,41.83) ; C201.1 42.69,30.63 v1(42.6,30.71) ; R183.1 70.11,64.34 70.45,64.69 v1(70.47,64.69) ; R218.1 70.28,16.01 v1(70.58,16.3) ; v1(56.99,61.51) 57.58,60.93 C56.1 ; C202.2 41.83,30.69 v1(41.8,30.71) ; R221.1 v1(70.79,11.44) ; R87.1 v1(4.88,39.8) R89.1 ; C101.1 C102.1 v1(67.63,73.45) ; R202.1 v1(92.55,41.83) ; v1(57.68,54.94) 58.26,55.52 R184.1 ; v1(5.39,79.29) R224.2 ; v1(41.65,45.87) 42.08,45.43 C125.2 C127.2 42.08,43.97 v1(41.65,43.53) ; R219.1 v1(70.62,14.74) ; R93.1 v1(4.75,35.23) ; R172.1 v1(67.02,75.54) ; J5.4 v1(74.01,77.52) ; R222.2 v1(4.41,81.58)
  vias: v1(4.03,92.88) v1(5.25,70.48) v1(7.59,92.88) v1(7.59,70.48) v1(9.37,92.88) v1(9.92,70.48) v1(12.26,70.48) v1(13.3,92.88) v1(14.75,70.48) v1(18.26,92.88) v1(32.1,17.19) v1(32.1,16.18) v1(43.29,66.26) v1(43.29,65.1) v1(44.54,65.1) v1(44.54,63.93) v1(45.68,65.1) v1(45.68,63.93) v1(46.8,66.26) v1(46.8,65.1) v1(46.8,63.93) v1(82.77,10.59) v1(83.41,11.48) v1(90.72,81.21) v1(90.72,80.04) v1(90.9,85.16) v1(90.9,83.99)
3V3_A: length 26.6
  TOP w0.381: C11.1 v1(48.86,91.74) ; R14.1 v1(50.01,91.74)
  L05_PWR1 w0.381: v1(46.83,69.39) 46.83,91.11 47.47,91.74 v1(48.86,91.74)
  L08_SIG2 w0.381: v1(50.01,91.74) v1(48.86,91.74)
5V: length 14.2
  TOP w0.381: D4.2 57.98,87.17 57.12,87.17 v1(57.12,87.17) ; v1(32.35,87.17) 33.22,87.17 D2.2 ; v1(31.03,93.14) R1.2 v1(31.72,92.38) ; v1(55.59,92.88) 55.59,92.16 R2.2 56.1,92.12 v1(56.36,92.38) ; D3.2 48.51,87.17 49.24,87.17 49.24,87.17 v1(49.37,87.17) ; v1(24.61,87.17) 24.48,87.17 24.48,87.17 23.74,87.17 D1.2 ; LD10.2 v1(33.88,93.52)
  TOP w0.457: U2.11 52.46,81.41 52.8,81.07 ; 28.03,81.07 27.69,81.41 U1.11 ; U1.14 29.64,81.41 29.3,81.07 ; 54.07,81.07 54.41,81.41 U2.14
  vias: v1(28.67,74.65) v1(28.8,75.87) v1(29.94,76.98) v1(29.94,75.82) v1(29.94,74.65) v1(30.04,79.32) v1(30.04,78.15) v1(31.21,79.32) v1(31.21,78.15) v1(31.21,76.98) v1(31.21,75.82) v1(31.21,74.65) v1(53.43,75.64) v1(53.43,74.47) v1(54.7,76.81) v1(54.7,75.64) v1(54.7,74.47) v1(54.81,79.14) v1(54.81,77.97) v1(55.97,79.14) v1(55.97,77.97) v1(55.97,76.81) v1(55.97,75.64) v1(55.97,74.47)
GND: length 355.7
  TOP w0.152: v1(93.82,72.06) 93.84,72.07 D9.3 ; D11.3 v1(94.07,22.91)
  TOP w0.254: v1(82.98,85.87) 83.06,85.95 U3.13 ; U3.11 83.22,84.95 v1(83.03,84.76) 83.03,84.7 83.28,84.45 U3.10 ; U13.3 39.97,19.64 39.72,19.89 v1(39.72,20.24) ; U3.25 v1(78.2,90.39) ; U3.5 v1(82.91,81.95) ; v1(82.98,87.04) 83.07,86.95 U3.15 ; U3.51 v1(75.7,79.63) ; U3.35 v1(74.09,86.45) ; U3.47 v1(73.87,80.45)
  TOP w0.305: J3.36 v1(14.51,27.04) ; J3.30 14.53,28.54 v1(14.45,28.62) ; J3.54 v1(14.55,22.54) ; U15.1 78.04,10.49 78.2,10.33 v1(78.2,9.83) ; U15.47 v1(64.81,10.99) ; J3.60 v1(14.55,21.04) ; U15.11 76.5,15.49 v1(75.91,16.07) 76.33,16.49 U15.13 ; J3.18 14.59,31.54 14.47,31.42 v1(13.94,31.42) ; U15.35 v1(64.85,16.99) ; v1(71.22,21.64) 71.47,21.38 U15.25 ; v1(69.18,7.34) 68.97,7.55 U15.51 ; J3.24 v1(14.46,30.04) ; U15.10 v1(78.62,14.99) ; J3.42 v1(14.55,25.54) ; U15.15 v1(76.09,17.49) ; U15.5 v1(76.04,12.49) ; J3.48 v1(14.55,24.04)
  TOP w0.356: U12.U9 v1(41.8,28.31) ; R44.2 v1(75.79,64.69) ; v1(64.69,49.78) 64.61,49.86 C69.2 ; C51.2 73.37,65.91 v1(73.35,65.88) ; U10.J9 v1(59.49,38.88) ; R59.1 56.51,51.92 v1(56.51,52.12) ; C30.2 v1(84.68,76.37) ; U12.G4 v1(37.8,37.11) ; D6.2 45.81,80.63 v1(45.81,81.71) ; U11.L1 79.26,40.08 v1(79.97,40.79) 80.17,40.59 80.67,40.59 C74.1 ; D13.2 v1(13.29,9.34) ; U12.Y8 v1(41,25.91) ; D12.2 v1(6.12,10.91) ; C17.2 v1(86.67,85.3) ; U12.Y12 v1(45,25.91) ; U11.D9 v1(71.3,34.08) ; SW4.3 3.17,31.67 v1(2.38,31.67) ; D14.2 v1(25,8.95) ; U8.3 34.51,49.77 v1(34.51,50.08) ; U12.V13 v1(45.8,27.51) ; v1(7.59,65.2) SW2.11 ; U12.F14 v1(46.6,37.11) U12.G14 ; U12.J7 v1(40.2,35.51) ; C29.2 v1(86.33,78.1) ; U12.G13 v1(45.8,37.11) U12.F13 ; v1(90.43,79) Y1.2 v1(91.49,77.85) ; R15.2 51.15,90.99 51.15,91.61 v1(51.02,91.74) ; U12.P13 v1(45.8,30.71) ; v1(20.92,7.16) 19.64,7.16 SW7.4 ; U12.Y14 v1(46.6,25.91) ; U10.L1 v1(66.69,40.48) ; v1(85.65,9.78) 85.27,9.4 Y3.2 ; U10.F8 v1(60.29,35.68) ; v1(14.45,7.29) 14.5,7.23 SW7.3 ; C35.2 93.26,72.99 v1(93.44,72.82) ; U10.A1 66.69,32.48 ; 66.69,32.48 U10.B1 ; 66.69,32.48 v1(66.69,32.48) ; U12.N14 v1(46.6,31.51) ; C81.1 v1(5.23,23.03) ; C61.2 56.66,59.31 56.23,59.74 v1(56.23,59.86) ; C44.2 73.37,70.63 v1(73.35,70.66) ; R46.2 55.25,61.09 v1(54.83,61.51) ; U7.4 29.43,54.15 28.82,53.54 v1(28.62,53.54) ; U10.N1 v1(66.69,42.08) ; U12.V6 v1(39.4,27.51) ; C94.2 v1(53.69,7.16) ; U11.B1 v1(78.5,32.48) ; C62.2 38.19,57.96 v1(38.6,57.55) ; U12.W6 v1(39.4,26.71) ; U12.V15 v1(47.4,27.51) ; U12.V19 v1(50.6,27.51) ; U12.U10 v1(42.6,28.31) ; v1(18.77,38.52) J3.61 v1(18.77,34.71) J3.62 v1(18.77,28.38) J3.63 v1(18.77,21.88) J3.64 v1(18.77,18.07) ; U12.N6 v1(40.2,31.51) U12.N7 ; v1(90.76,82.46) 90.38,82.08 R25.1 ; R155.2 85.63,11.28 v1(85.82,11.48) ; U12.Y16 v1(48.2,25.91) ; U12.Y15 v1(47.4,25.91) ; U12.K14 v1(46.6,34.71) ; C85.2 v1(82.22,17.15) ; U12.J10 v1(42.6,35.51) ; C3.2 v1(51.02,92.98) ; R49.2 38.3,56.69 v1(38.6,56.38) ; U12.Y7 v1(40.2,25.91) ; U10.J1 66.69,38.88 v1(66.81,38.88) ; C70.2 65.75,49.88 v1(65.86,49.78) ; U11.D8 v1(72.1,34.08) ; U11.N9 v1(71.3,42.08) ; C24.2 v1(88.59,79.57) ; C15.2 69.55,86.13 v1(69.89,86.46) ; C16.2 v1(88.59,86.06) ; U10.N9 v1(59.49,42.08) ; U12.V20 v1(51.4,27.51) ; U12.G17 v1(49,37.11) ; C14.2 86.27,87.36 v1(86.9,88) ; U11.A8 v1(72.1,31.68) ; U5.4 52.58,61.73 53.07,61.25 v1(53.33,61.25) ; C87.2 v1(63.98,15.16) ; U10.F2 v1(65.89,36.48) ; U12.M12 v1(45,32.31) ; C59.2 73.71,58.77 v1(74.26,58.21) ; v1(11.4,65.2) SW2.14 ; C96.1 v1(25.1,7.3) ; U12.K10 v1(42.6,34.71) ; U12.V5 v1(38.6,27.51) ; v1(93.31,22.4) 93.31,22.53 93.39,22.6 C80.1 ; R135.2 90.34,19.99 v1(91.1,20.75) ; D7.2 36.03,81.45 v1(36.04,81.45) ; v1(75.58,61.11) 75.3,61.39 C55.2 ; U12.J9 v1(41.8,35.51) ; v1(75.58,62.53) 75.33,62.78 C54.2 ; U12.Y17 v1(49,25.91) ; R56.1 61.18,51.27 v1(61.18,52.12) ; C82.2 v1(66.77,21.64) ; U10.L9 v1(59.49,40.48) ; C50.1 v1(94.28,69.36) ; U12.V12 v1(45,27.51) ; C8.2 v1(75.2,93.09) ; U10.C9 v1(59.49,33.28) ; C23.2 v1(86.33,79.42) ; U12.Y5 v1(38.6,25.91) ; Q1.2 v1(85.94,27.1) ; C1.2 v1(26.23,92.98) ; R13.2 26.38,90.99 26.38,91.59 v1(26.23,91.74) ; U12.L9 v1(41.8,33.11) ; U12.B7 v1(40.2,41.11) ; U12.L12 v1(45,33.11) ; S1.4 v1(30.83,6.52) ; C83.2 v1(72.36,21.64) ; C71.2 v1(67.15,49.96) ; U10.A8 v1(60.29,31.68) ; U12.U11 v1(44.2,28.31) ; U4.5 v1(92.3,69.7) ; C53.2 56.18,65.83 v1(56.65,66.3) ; SW4.4 v1(2.25,27.56) ; U11.A1 v1(78.5,31.68) ; U12.G10 v1(42.6,37.11) ; C56.2 v1(55.97,60.75) ; U12.V16 v1(48.2,27.51) ; U12.P11 v1(44.2,30.71) ; SW6.4 v1(8.73,7.57) ; U12.W19 v1(50.6,26.71) ; U11.F2 v1(76.9,35.68) ; v1(12.67,65.2) SW2.15 ; U12.K6 v1(39.4,34.71) ; D5.2 v1(19.14,80.56) ; U12.V7 v1(40.2,27.51) ; U12.J2 v1(36.2,35.51) ; U12.W20 v1(51.4,26.71) ; C9.2 v1(79.89,92.21) ; U12.Y6 v1(39.4,25.91) ; U11.B2 v1(77.7,32.48) ; U12.U8 v1(41,28.31) ; U10.D9 v1(59.49,34.08) ; U12.J11 v1(44.2,35.51) ; U12.M9 v1(41.8,32.31) ; U12.V9 v1(41.8,27.51) ; U12.N15 v1(47.4,31.51) ; U12.G8 v1(41,37.11) ; C75.1 80.51,39.04 v1(80.11,39.04) 79.55,38.48 U11.J1 ; v1(6.32,65.2) SW2.10 ; U12.U13 v1(45.8,28.31) ; U12.G7 v1(40.2,37.11) ; U3.1 v1(83.04,79.95) ; C7.2 v1(73.95,93.07) ; U12.U12 v1(45,28.31) ; U12.M11 v1(44.2,32.31) ; C31.2 v1(86.28,75.28) ; U12.C19 v1(50.6,40.31) ; U11.L9 v1(71.3,40.48) ; U12.R19 v1(50.6,29.91) ; U12.P12 v1(45,30.71) ; C86.2 v1(79.82,17.35) ; Y3.4 82.1,7.2 82.1,7.2 v1(81.97,7.2) ; U12.F8 v1(41,37.91) U12.F7 ; v1(10.13,65.2) SW2.13 ; U12.Y19 v1(50.6,25.91) ; S1.3 v1(29.56,6.52) ; v1(75.53,58.21) 74.98,58.77 C60.2 ; v1(69.82,82.09) 69.88,82.03 C22.2 ; U11.J9 v1(71.3,38.88) ; U12.K15 v1(47.4,34.71) ; C95.1 v1(11.34,8.36) ; U12.G6 v1(39.4,37.11) ; C84.1 v1(35.65,18.46) ; U12.P7 v1(40.2,30.71) ; U11.C9 v1(71.3,33.28) ; v1(87.83,75.61) 87.85,75.61 87.89,75.65 Y1.4 v1(88.83,74.43) ; U10.D1 v1(66.69,34.08) ; v1(8.86,65.2) SW2.12 ; U10.D8 v1(60.29,34.08) ; U12.G15 v1(47.4,37.11) ; U11.N1 v1(78.5,42.08) ; v1(13.94,65.2) SW2.16 ; U12.J14 v1(46.6,35.51) ; R42.1 v1(80.26,68.88) ; U10.B2 v1(65.89,32.48) ; U12.P8 v1(41,30.71) ; D8.2 v1(61.73,80.52) ; U12.V8 v1(41,27.51) ; U12.J12 v1(45,35.51) ; U12.L10 v1(42.6,33.11) ; C92.2 v1(53.69,8.3) ; U12.G11 v1(44.2,37.11) ; C65.2 75.49,56.65 v1(75.53,56.69) ; U11.F8 v1(72.1,35.68) ; U12.U7 v1(40.2,28.31) ; U2.5 v1(53.11,89.53) ; U12.Y11 v1(44.2,25.91) ; U12.K11 v1(44.2,34.71) ; U12.G9 v1(41.8,37.11) ; C93.2 v1(80.28,6.95) ; D10.2 6.38,22.49 5.9,22.02 v1(5.3,22.02) ; R18.2 v1(34.07,89.78) ; C49.1 v1(91.54,68.62) ; S1.2 v1(28.29,6.52) ; U12.G12 v1(45,37.11) ; U12.U14 v1(46.6,28.31) ; U12.W16 v1(48.2,26.71) ; U12.W15 v1(47.4,26.71) ; U10.B8 v1(60.29,32.48) ; U12.K9 v1(41.8,34.71) ; U12.H19 v1(50.6,36.31) ; U12.M7 v1(40.2,32.31) ; R19.2 v1(58.77,89.78) ; SW6.3 v1(2.13,7.57) ; v1(5.05,65.2) SW2.9 ; U12.B14 v1(46.6,41.11) ; U11.D1 v1(78.5,34.08) ; U12.D4 v1(37.8,39.51) ; U12.W12 v1(45,26.71) ; U12.P14 v1(46.6,30.71) ; U12.M10 v1(42.6,32.31) ; U12.K7 v1(40.2,34.71) ; U12.K12 v1(45,34.71) ; U12.M2 v1(36.2,32.31) ; U12.L11 v1(44.2,33.11) ; U12.V14 v1(46.6,27.51) ; U11.B8 v1(72.1,32.48) ; U12.M14 v1(46.6,32.31) ; U12.M16 v1(48.2,32.31) ; C89.1 v1(5.14,11.76) ; SW5.4 v1(3.21,15.03) ; U12.W7 v1(40.2,26.71)
  TOP w0.381: C216.2 v1(70.07,6.52) C98.2 69.39,7.13 v1(69.18,7.34) ; U9.3 28.51,37.22 28.42,37.13 v1(28.29,37.13) ; v1(55.97,58.6) 56.02,58.6 C106.2 ; J1.5 96.63,72.68 v1(96.36,72.94) ; J4.5 96.9,24.53 v1(96.61,24.81) ; v1(28.29,91.36) 28.21,91.28 C2.2 ; SW1.4 v1(13.05,80.31) ; C97.2 65.25,6.84 v1(65.25,7.79) ; J4.4 96.83,23.88 v1(96.74,23.8) ; v1(78.19,74.48) 78.2,74.48 C34.2 ; v1(30.45,42.85) 30.07,42.46 29.94,42.46 ; v1(75.53,55.67) 75.41,55.67 74.85,55.12 C67.2 ; C12.2 v1(31.34,91.61) ; SW5.3 v1(3.21,21.38) ; C4.2 52.93,90.68 v1(52.93,91.23) ; 29.94,42.46 v1(29.43,42.97) ; 29.94,42.46 C73.2 ; v1(38.58,46.53) 38.58,46.25 C72.2 ; SW1.6 v1(13.05,82.85) ; C33.2 v1(76.54,75.24) ; C32.2 v1(74.71,75.26) ; v1(28.29,89.58) 28.34,89.53 U1.5 ; SW1.5 v1(13.05,81.58) ; U14.10 v1(58.39,20.87) ; v1(56.56,91.53) C13.2 ; R66.1 v1(60.2,48.27)
  L02_GND1 w0.381: v1(23.97,30.02) 24.35,30.4 24.48,30.4
  BOTTOM w0.279: 93.31,36.92 v1(93.31,37.34) ; v1(93.31,37.34) 92.81,36.84 U19.4 ; v1(93.31,37.34) U19.8
  BOTTOM w0.305: U16.5 v1(74.01,73.45)
  BOTTOM w0.356: C137.1 50.72,40.2 v1(50.6,40.31) ; C125.1 40.99,45.21 v1(40.48,44.7) ; v1(65.89,36.48) 65.9,36.47 C152.2 ; C200.1 44.64,30.35 44.77,30.48 44.77,30.49 v1(45,30.71) ; v1(42.6,33.11) 42.8,33.11 43.22,33.53 C183.2 43.71,33.22 44.1,33.22 v1(44.2,33.11) 44.24,33.15 44.24,33.79 C173.1 44.24,34.04 44.24,34.68 v1(44.2,34.71) 44.13,34.64 C160.2 42.68,34.64 v1(42.6,34.71) 42.59,34.7 42.59,34.21 C171.1 42.59,33.7 42.59,33.12 v1(42.6,33.11) ; v1(42.6,33.11) v1(41.8,33.11) ; v1(71.3,42.08) 70.76,42.08 C129.2 ; v1(46.6,37.11) 46.66,37.17 C147.2 ; v1(66.69,34.08) 66.69,34.08 C178.2 ; C169.1 60.83,34.08 60.82,34.08 v1(60.29,34.08) ; C191.1 v1(53.39,31.72) ; v1(77.31,58.72) U17.8 U17.3 v1(79.72,58.72) ; v1(71.3,40.48) 71.28,40.46 C134.1 ; v1(46.6,30.71) 46.5,30.61 C199.2 ; C138.1 66.95,39.01 v1(66.81,38.88) ; C197.2 v1(60.83,30.17) ; C61.2 56.23,59.66 v1(56.23,59.86) ; v1(36.2,32.31) 36.21,32.31 C194.1 ; C56.2 v1(55.97,60.75) ; v1(74.01,39.3) 73.69,39.3 73.3,38.91 C139.2 ; C201.2 44.03,30.45 44.03,30.46 44.06,30.49 44.06,30.58 v1(44.2,30.71) 44.09,30.83 43.45,30.83 C188.1 ; v1(78.5,31.68) 78.44,31.62 C189.2 ; v1(44.2,35.51) 44.35,35.37 44.85,35.37 v1(45,35.51) ; v1(72.1,31.68) 72.22,31.55 C192.1 ; v1(59.49,34.08) 58.88,34.08 C165.2 ; v1(44.2,28.31) 43.92,28.03 C206.1 42.88,28.03 v1(42.6,28.31) ; v1(56.23,55.29) 56.48,55.29 R185.1 ; U18.8 U18.3 v1(79.72,55.04) ; v1(66.69,40.48) 67.6,40.48 67.66,40.53 C130.2 ; J5.12 v1(66.79,89.05) ; v1(36.2,28.31) 36.2,29.12 C205.2 ; v1(66.69,31.68) 66.75,31.62 66.75,31.11 C193.2 ; C166.1 35.61,34.92 v1(36.2,35.51) ; C54.2 75.33,62.78 v1(75.58,62.53) ; U20.5 v1(60.63,12.2) ; C168.1 72.13,34.11 v1(72.1,34.08) ; v1(41,30.71) 40.91,30.62 C202.1 ; C155.2 59.96,36.09 60.29,35.76 v1(60.29,35.68) ; C203.2 40.15,30.67 v1(40.2,30.71) ; v1(75.53,58.21) 75.4,58.21 C60.2 ; C127.1 41.14,44.19 v1(40.48,43.53) ; C135.2 58.77,40.37 58.88,40.48 v1(59.49,40.48) ; v1(60.29,31.68) 60.31,31.65 60.31,31.15 C190.2 ; v1(78.5,34.08) 79.42,34.08 C162.1 ; J5.6 v1(71.81,77.43) ; C146.1 75.66,37.89 75.53,38.02 v1(75.53,38.08) ; C128.1 58.86,42.08 v1(59.49,42.08) ; v1(46.6,25.91) 46.6,25.47 46.5,25.37 C209.1 ; v1(46.6,34.71) 46.83,34.49 46.83,34.48 47.06,34.25 C172.2 47.07,33.91 47.18,33.8 47.84,33.8 C176.1 47.89,34.22 v1(47.4,34.71) ; v1(71.3,34.08) 70.81,34.08 C164.1 ; C198.2 v1(67.13,30.04) ; v1(78.5,32.48) 78.93,32.48 C184.1 ; v1(50.6,33.11) 50.85,33.36 C177.2 ; v1(76.9,35.68) 76.52,35.3 C161.1 ; C170.1 65.12,33.24 v1(65.89,32.48) ; v1(54.02,29.54) 53.79,29.76 C204.2 ; C215.2 v1(59.33,15.09) ; C131.2 v1(94.92,41.87) ; v1(44.2,37.11) 43.98,37.34 C151.1 ; C132.1 v1(91.41,41.83) ; C143.1 50.04,38.48 v1(49.8,38.71) ; C111.2 v1(67.15,49.96) ; v1(72.1,35.68) 71.76,36.01 C154.2 ; v1(59.49,38.88) 59.52,38.91 C140.1 ; C186.2 58.95,33.28 v1(59.49,33.28) ; C185.1 70.8,33.28 v1(71.3,33.28)
  BOTTOM w0.381: C149.1 48.52,37.59 v1(49,37.11) ; v1(85.44,45) 85.44,45.55 R190.2 ; R206.2 58.34,38.03 58.32,38.03 58.06,38.28 v1(58.06,38.88) ; C144.2 38.64,38 C153.1 ; R205.2 70.54,38.74 70.68,38.88 v1(71.3,38.88) ; v1(55.09,49.7) 54.83,49.96 R187.1 ; v1(35.78,92.63) 35.62,92.8 R21.2 ; v1(40.2,34.71) v1(40.2,35.51) ; v1(37.8,37.11) 37.83,37.08 C153.1 ; C67.2 75.48,55.67 v1(75.53,55.67) ; D15.2 v1(67.02,76.75) ; C101.2 69.56,71.98 v1(69.23,71.65) ; v1(50.6,25.91) 50.59,25.91 C214.1 ; C153.1 38.67,37.11 v1(39.4,37.11) ; v1(68.07,71.65) 68.42,72.01 C102.2 ; C213.2 50.39,26.8 50.47,26.71 v1(50.6,26.71) v1(51.4,26.71) ; R196.2 v1(93.06,43.48) ; C163.2 v1(75.53,34) ; v1(39.4,34.71) 39.64,34.48 C174.2 ; C159.2 68.93,34.67 v1(68.93,34.34) ; R188.1 v1(53.69,49.83)
  vias: v1(6.44,21.51) v1(6.95,31.03) v1(7.46,24.81) v1(8.35,35.23) v1(8.6,32.18) v1(9.75,24.3) v1(9.75,23.03) v1(9.9,39.25) v1(9.9,38.08) v1(11.02,35.1) v1(11.07,39.25) v1(11.07,38.08) v1(11.4,27.86) v1(11.4,25.32) v1(11.89,22.16) v1(12.16,26.97) v1(12.54,40.56) v1(12.65,24.06) v1(13.43,26.97) v1(14.45,34.46) v1(15.97,73.61) v1(15.97,72.44) v1(15.97,71.27) v1(15.97,70.1) v1(15.97,68.93) v1(17.14,68.93) v1(19.65,39.42) v1(19.65,36.75) v1(21.18,40.56) v1(22.95,39.8) v1(24.61,32.43) v1(24.61,31.67) v1(24.73,26.46) v1(24.86,27.48) v1(25.24,39.04) v1(25.24,38.15) v1(26.23,74.65) v1(26.51,75.87) v1(27.4,86.75) v1(27.4,85.48) v1(27.4,84.21) v1(27.4,75.82) v1(27.4,73.61) v1(27.4,71.4) v1(28.42,42.97) v1(28.42,31.67) v1(28.54,46.78) v1(28.62,51.2) v1(28.62,48.87) v1(28.67,86.75) v1(28.67,85.48) v1(28.67,84.21) v1(28.67,72.56) v1(28.67,70.23) v1(28.67,30.53) v1(28.67,26.84) v1(28.8,19.73) v1(29.79,52.37) v1(29.79,50.03) v1(29.79,47.7) v1(29.79,45.36) v1(29.79,44.19) v1(29.94,86.75) v1(29.94,85.48) v1(29.94,84.21) v1(29.94,73.61) v1(30.19,18.33) v1(31.08,29.38) v1(31.08,27.48) v1(31.59,24.3) v1(31.84,34.21) v1(31.97,30.65) v1(33.02,35.99) v1(32.99,24.68) v1(33.75,21.76) v1(33.88,22.53) v1(37.94,22.4) v1(38.3,73.61) v1(38.3,69.06) v1(39.21,22.53) v1(39.46,72.56) v1(39.46,70.23) v1(40.73,73.61) v1(40.73,71.4) v1(40.73,69.06) v1(41.65,48.21) v1(41.75,22.53) v1(42.21,62.23) v1(42.21,59.89) v1(43.38,61.06) v1(43.38,58.72) v1(44.54,62.23) v1(44.54,59.89) v1(45.68,61.06) v1(47.97,67.43) v1(47.97,66.26) v1(47.97,65.1) v1(47.97,63.93) v1(49.88,46.78) v1(51.02,75.61) v1(51,74.47) v1(51,64.05) v1(51,63.04) v1(51,54.05) v1(51,52.88) v1(51.4,48.56) v1(51.66,58.34) v1(51.91,71.67) v1(52.04,46.02) v1(52.16,86.75) v1(52.16,85.48) v1(52.16,84.21) v1(52.16,75.64) v1(52.16,73.61) v1(52.16,64.05) v1(52.16,63.04) v1(52.16,52.88) v1(53.18,21.38) v1(53.33,54.05) v1(53.33,52.88) v1(53.43,86.75) v1(53.43,85.48) v1(53.43,84.21) v1(53.43,72.69) v1(53.43,70.23) v1(53.56,57.96) v1(54.07,47.16) v1(54.32,21.38) v1(54.7,86.75) v1(54.7,85.48) v1(54.7,84.21) v1(54.7,63.67) v1(55.34,25.45) v1(55.97,63.67) v1(57.88,62.28) v1(61.05,69.31) v1(61.44,92.5) v1(61.44,90.98) v1(62.96,93.01) v1(63.09,90.47) v1(63.39,69.31) v1(64.1,61.6) v1(64.1,59.82) v1(64.1,58.04) v1(64.56,72.82) v1(64.56,70.48) v1(65.73,69.31) v1(65.88,61.6) v1(65.88,59.82) v1(65.88,58.04) v1(66.26,26.21) v1(66.26,25.32) v1(66.9,70.48) v1(67.53,25.32) v1(67.66,61.6) v1(67.66,59.82) v1(67.66,58.04) v1(68.07,69.31) v1(69.31,25.32) v1(70.2,48.81) v1(70.83,26.21) v1(71.85,64.69) v1(72.54,48.81) v1(72.99,76.12) v1(74.64,52.88) v1(74.87,48.81) v1(75.53,54.28) v1(76.29,51.99) v1(76.42,57.96) v1(76.68,64.82) v1(77.21,48.81) v1(77.44,53.39) v1(77.69,64.82) v1(78.07,60.75) v1(78.58,56.94) v1(78.96,52.75) v1(79.47,50.72) v1(79.55,48.81) v1(79.77,10.71) v1(80.36,32.3) v1(80.36,30.91) v1(80.49,9.83) v1(81.25,31.67) v1(82.26,32.3) v1(82.52,49.7) v1(83.91,32.3) v1(86.07,39.92) v1(86.07,38.4) v1(86.07,36.75) v1(87.64,33.3) v1(87.64,32.13) v1(88.81,32.13) v1(89.98,32.13) v1(91.14,32.13) v1(92.31,32.13) v1(92.42,37.89) v1(92.42,36.75) v1(93.83,75.95) v1(94.2,37.89) v1(94.2,36.75) v1(94.33,28.37) v1(94.33,27.22) v1(94.58,76.75) v1(96.73,26.98) v1(96.87,39.19) v1(96.87,34.51) v1(96.87,33.35) v1(96.87,32.18) v1(98.04,39.19) v1(98.04,34.51) v1(98.04,33.35) v1(99.21,39.19) v1(99.21,38.02) v1(99.21,36.85) v1(99.21,35.68) v1(99.21,34.51) v1(99.21,33.35) v1(100.37,39.19) v1(100.37,38.02) v1(100.37,36.85) v1(100.37,35.68) v1(100.37,34.51) v1(100.37,33.35)
GND_SDCD: length 5.8
  BOTTOM w0.381: v1(83.03,93.65) J5.14 81.21,93.39 81.59,93.01 v1(82.26,93.01) ; J5.11 v1(66.77,82.85) ; J5.10 v1(78.86,77.03)
  vias: v1(66.52,93.01) v1(66.52,91.99) v1(66.52,90.85)
VCC_1V1: length 25.7
  TOP w0.381: v1(23.34,90.98) 24.02,90.98 C10.1 ; R12.1 v1(25.24,91.74)
  L08_SIG2 w0.381: v1(25.24,91.74) 24.48,90.98 v1(23.34,90.98) 21.94,89.58 v1(21.94,69.64)
VCC_AUX: length 8.9
  TOP w0.356: U12.V11 v1(44.2,27.51) ; U12.V17 v1(49,27.51) ; U12.P15 v1(47.4,30.71) ; U12.P6 v1(39.4,30.71) ; U12.F6 v1(40.2,37.91) ; U12.V10 v1(42.6,27.51) ; U12.V18 v1(49.8,27.51) ; U12.F15 v1(47.4,37.91)
  L08_SIG2 w0.381: v1(49,27.51) 49,26.86 ; v1(49.8,27.51) 49.8,26.86
  BOTTOM w0.381: C203.1 39.23,30.31 39.4,30.47 v1(39.4,30.71) ; v1(47.4,30.71) 47.4,30.04 C199.1 ; v1(40.2,37.91) 40.1,38.02 C144.1 ; v1(49,39.51) 49.77,39.51 C137.2
  vias: v1(30.96,45.39) v1(30.96,44.24) v1(32.1,45.36) v1(32.1,44.19) v1(33.27,45.36) v1(33.27,44.19) v1(34.51,43.99)
VCC_CORE: length 26
  TOP w0.356: U12.H10 v1(42.6,36.31) ; U12.H12 v1(45,36.31) ; U12.N10 v1(42.6,31.51) ; U12.H8 v1(41,36.31) ; U12.H9 v1(41.8,36.31) ; U12.J8 v1(41,35.51) ; U12.N13 v1(45.8,31.51) ; U12.N8 v1(41,31.51) ; U12.N9 v1(41.8,31.51) ; U12.J13 v1(45.8,35.51) ; U12.N12 v1(45,31.51) ; U12.K13 v1(45.8,34.71) ; U12.L13 v1(45.8,33.11) ; U12.M8 v1(41,32.31) ; U12.H13 v1(45.8,36.31) ; U12.L8 v1(41,33.11) ; U12.K8 v1(41,34.71) ; U12.N11 v1(44.2,31.51) ; U12.H11 v1(44.2,36.31) ; U12.M13 v1(45.8,32.31)
  BOTTOM w0.381: v1(41.8,36.31) v1(41,36.31) v1(41,35.51) v1(41,34.71) ; C160.1 C151.2 42.71,36.42 v1(42.6,36.31) ; C188.2 43.45,31.75 43.97,31.75 v1(44.2,31.51) v1(45,31.51) v1(45.8,31.51) v1(45.8,32.31) v1(45.8,33.11) ; C188.2 43.35,31.75 42.84,31.75 v1(42.6,31.51) v1(41.8,31.51) v1(41,31.51) v1(41,32.31) v1(41,33.11) ; C188.2 C183.1 ; v1(45.8,34.71) v1(45.8,35.51) v1(45.8,36.31)
  vias: v1(20.77,66.26) v1(20.77,65.1) v1(20.77,63.93) v1(21.94,65.1) v1(21.94,63.93) v1(23.11,65.1) v1(23.11,63.93) v1(24.22,66.09) v1(24.28,65.1) v1(24.28,63.93)
VCCHTX: length 2.9
  TOP w0.356: U12.U6 v1(39.4,28.31) ; U12.T6 v1(39.4,29.11) ; U12.T15 v1(47.4,29.11) ; U12.U15 v1(47.4,28.31)
  BOTTOM w0.381: C209.2 v1(48.05,24.81)
  vias: v1(37.94,24.81) v1(39.34,24.81) v1(40.23,25.07) v1(47.29,53.01) v1(47.29,51.84) v1(48.53,53.01) v1(48.53,51.84)
VCCHTX_1V1: length 1.9
  TOP w0.381: R45.1 52.67,59.61 52.59,59.53 C58.1 51.32,59.53
VCCHTX_C: length 10.5
  TOP w0.356: U12.T12 v1(45,29.11) ; U12.T7 v1(40.2,29.11) ; U12.T11 v1(44.2,29.11) ; U12.T8 v1(41,29.11) ; U12.T13 v1(45.8,29.11) ; U12.T9 v1(41.8,29.11) ; U12.T14 v1(46.6,29.11) ; U12.T10 v1(42.6,29.11)
  BOTTOM w0.381: v1(45.8,29.11) 45.8,29.4 45.56,29.64 C200.2 ; v1(45.8,29.11) v1(45,29.11) v1(44.2,29.11) 44.04,28.95 C206.2 42.76,28.95 v1(42.6,29.11) v1(41.8,29.11) ; v1(45.8,29.11) v1(46.6,29.11)
  vias: v1(41.24,24.94) v1(42.26,24.81) v1(43.78,24.81)
12MHZ_OSCI: length 10.8
  TOP w0.14: U3.2 84.95,80.45 85.18,80.21 85.18,76.88 85.87,76.2 C31.1 87.63,76.2 88.19,76.75 89.43,76.75 90.43,75.76 Y1.1
12MHZ_OSCI1: length 10.5
  TOP w0.14: Y3.1 84.59,8.16 84.45,8.3 82.26,8.3 81.83,7.87 C93.1 79.9,7.87 78.71,9.06 78.71,10.59 78.3,10.99 U15.2
12MHZ_OSCO: length 8.5
  TOP w0.14: Y1.3 87.97,77.85 87.85,77.73 87.85,77.31 87.72,77.18 C29.1 85.9,77.18 85.69,77.39 85.69,80.2 84.95,80.95 U3.3
12MHZ_OSCO1: length 7.6
  TOP w0.14: U15.3 78.44,11.49 79.09,10.84 79.09,9.57 79.8,8.86 C91.1 82.44,8.86 Y3.3
